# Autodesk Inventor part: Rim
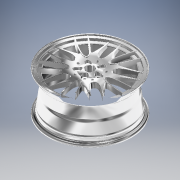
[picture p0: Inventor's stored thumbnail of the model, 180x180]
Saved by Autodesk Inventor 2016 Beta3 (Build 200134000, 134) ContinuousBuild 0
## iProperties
Shininess: 64.0
Length Units: 11269
Angle Units: 11279
Time Units: 11290
Mass Units: 11283
Length Display Precision: 3
Angle Display Precision: 2
Compacted: True
Part Number: Rim
Document SubType Name: Modeling
Created: 2003-06
Manufacturer: Standard
Standards Organization: Custom
Density: 2.71 g/cm^3
Material: Aluminum-6061
Mass: 9948.11 g
Surface Area: 8992.46 cm^2
Volume: 3670.89 cm^3
Appearance: Chrome - Polished
Density: 0.0
Volumn: 0.0
Area: 0.0
PropertySet Name: Model Information
Control State: 0
Master: False
Checked Out: False
Author: Autodesk, Inc.
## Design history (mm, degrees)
workplane "Work Plane4"
workplane "Work Plane1"
sketch "Spoke Side"
  geometry: L1 (0, -11162.344)-(0, 13420.953) reference; L2 (-1298.767, 0)-(7792.602, 0) reference; L3 (0, 55)-(10.286, 55); L4 (205.698, 37.987)-(254.302, 42.013); L5 (37.4, 37.385)-(62.6, 42.615); L6 (0, 0)-(60, 0); L7 (60, 0)-(60, 5); L8 (60, 5)-(65.959, 10); L9 (62.17, 6.821)-(69.748, 13.179); L10 (222.425, 21.138)-(237.575, 18.862); L11 (230, 40)-(230, 20); L12 (0, 55)-(0, 0); A1 r 209.241 centre (212.724, 248.526) between (210.568, 39.297) and (249.283, 42.504); A2 r 109.305 centre (27.793, 147.025) between (39.866, 38.389) and (59.938, 42.554); A3 r 90.833 centre (0, -35.833) between (50, 40) and (0, 55); A4 r 10000 centre (6493.835, -7650.444) between (68.99, 12.543) and (68.985, 12.55); A5 r 10000 centre (1715.468, 9909.054) between (223.941, 20.912) and (236.06, 19.092); 2 further points
  constraints: 20 end point, 8 midpoint, 6 point on circle, 5 centre point, 2 collinear, 2 parallel, 2 point on line, 1 perpendicular, 1 tangent, 14 other
  dimensions: "d1" = 55 distance between parallel lines of L2 L3; "d3" = 460 diameter of L11.start L1; "d4" = 40 distance from line of L2 L11.start; "d5" = 100 diameter of A3.start L1; "d6" = 50 distance from line of L2 point (110.655, 50); "d7" = 40 distance from line of L2 A3.start; "d8" = 60 distance of L6.start L6.end; "d9" = 0 distance between parallel lines of L2 L6; "d10" = 5 distance of L6.end L7.end; "d11" = 460 diameter of L11.end L1 (= d3); "d12" = 130 deg angle of L7 L8; "d13" = 5 vertical distance of L7.end L8.end; "d14" = 20 distance of L11.start L11.end
revolve "Revolution1" stored, may be unused: angle "d15" = 90 deg
sketch "Spoke Top"
  geometry: L1 (0, 35.567)-(0, -35.567) reference; L2 (-329.417, 0)-(-41.965, 0) reference; A1 r 22.668 centre (-265.684, 0) between (-282.023, 15.713) and (-282.023, -15.713); 5 further points
  constraints: 3 symmetric about line, 2 point on circle, 1 centre point, 1 point on line, 7 other
  dimensions: "d137" = 85 distance from line of L1 point (-85, 0); "d138" = 30 distance of point (-95.703, -15) point (-95.703, 15); "d139" = 40 distance of point (-231.71, -20) point (-231.71, 20)
extrude "Extrusion9" cut sketch "Spoke Top" stored distance "d141" = 10; taper "d142" = -5 deg
pattern_circular "Circular Pattern6" dims angle "d145" = 360 deg
sketch "Sketch19"
  geometry: L1 (-50, 0)-(-86.059, 0) reference; L2 (-437.715, 0)-(341.286, 0) reference; L3 (0, 398.906)-(0, -364.894) reference; L4 (0, 0)-(-268.128, 194.806) reference; L5 (-101.443, 282.759)-(-96.692, 201.808); L6 (-221.81, 29.598)-(-300.268, 9.1); A1 r 230 centre (0, 0) between (196.304, -119.853) and (196.304, 119.853) reference; A2 r 230 centre (0, 0) between (174.648, 149.66) and (-53.325, 223.733) reference; A3 r 230 centre (0, 0) between (-88.366, 212.348) and (-229.261, 18.422) reference; A4 r 230 centre (0, 0) between (-229.261, -18.422) and (-88.366, -212.348) reference; A5 r 230 centre (0, 0) between (-53.325, -223.733) and (174.648, -149.66) reference; A6 r 130.796 centre (31.504, 249.946) between (-95.482, 281.288) and (-90.944, 203.966); A7 r 130.796 centre (-227.977, -107.2) between (-222.087, 23.464) and (-297.026, 3.886); A8 r 157.848 centre (-117.742, 85.544) between (-99.068, 242.284) and (-261.039, 19.349); 10 further points
  constraints: 6 end point, 4 midpoint, 4 point on circle, 3 centre point, 3 symmetric about line, 1 horizontal alignment, 1 point on line, 13 other
  dimensions: "d147" = 100 distance of A1.centre point (-80.902, 58.779); "d148" = 10 dimension on L6.start L6.end (= d149); "d149" = 10 dimension on L5.start L5.end
extrude "Extrusion10" cut sketch "Sketch19" stored distance "d150" = 10; taper "d151" = -5 deg
pattern_circular "Circular Pattern7" dims angle "d154" = 360 deg
sketch "Sketch20"
  geometry: L1 (-300.487, 0)-(50.081, 0) reference; L2 (0, 230.697)-(0, -38.449) reference; L3 (0, 0)-(-250.021, 181.651) reference; L4 (-230.266, 187.463)-(-204.629, 181.002); L5 (-235.377, 138.681)-(-249.444, 161.066); A1 r 50.044 centre (-229.678, 135.707) between (-205.46, 179.5) and (-230.246, 185.747); A2 r 50.044 centre (-200.039, 176.501) between (-247.806, 161.578) and (-234.205, 139.935); A3 r 27.755 centre (-215.47, 156.548) between (-217.447, 184.233) and (-242.411, 149.874); 5 further points
  constraints: 6 end point, 4 midpoint, 4 point on circle, 3 centre point, 3 point on line, 3 symmetric about line, 13 other
  dimensions: "d157" = 80 distance of L3.start point (-64.721, 47.023); "d158" = 285 distance of L3.start A3.start; "d159" = 5 dimension on L4.start L4.end; "d160" = 5 dimension on L5.start L5.end (= d159); "d161" = 22 distance of point (-76.988, 42.339) point (-64.057, 60.137)
extrude "Extrusion12" join sketch "Sketch20" distance "d164" = 40; taper "d165" = 5 deg
sketch "Sketch21" dims "d166" = 5
  geometry: L1 (0, 0)-(-271.586, 197.319); A1 r 27.755 centre (-215.47, 156.548) between (-217.447, 184.233) and (-242.411, 149.874) reference; 3 further points
  constraints: 2 end point, 2 point on line, 7 other
extrude "Extrusion13" cut sketch "Sketch21" stored distance "d167" = 20; taper "d168" = -1 deg
pattern_circular "Circular Pattern8" dims angle "d171" = 360 deg
sketch "Sketch22"
  geometry: L1 (60, 0)-(60, 5) reference; L2 (60, 5)-(65.959, 10) reference; L3 (60, 0)-(60, -25.42); L4 (60, -25.42)-(230, -25.42); L5 (230, -25.42)-(230, 20); L6 (0, 55)-(0, 0) reference
  constraints: 6 end point, 1 collinear, 1 parallel, 1 perpendicular
revolve "Revolution3" sketch "Sketch22" stored, may be unused: angle "d172" = 90 deg
sketch "Sketch23"
  geometry: C1 r 225 at (0, 0); C2 r 325 at (0, 0); 1 further point
  constraints: 2 centre point, 2 coincident
  dimensions: "d173" = 450 diameter of C1; "d174" = 650 diameter of C2
extrude "Extrusion14" cut sketch "Sketch23" stored distance "d175" = 20; taper "d176" = 0 deg
workplane "Work Plane5"
sketch "Sketch24"
  geometry: L1 (0, 202.622)-(0, -33.77) reference; L2 (-278.885, 0)-(46.481, 0) reference; L3 (0, 0)-(-232.404, 168.851) reference; C1 r 12.5 at (-36.406, 26.45); 4 further points
  constraints: 5 point on line, 2 end point, 1 centre point, 1 symmetric about line, 5 other
  dimensions: "d179" = 25 diameter of C1; "d180" = 45 distance of L3.start C1.centre; "d181" = 28 distance of L3.start point (-22.652, 16.458); "d182" = 70 distance of L3.start point (-56.631, 41.145); "d183" = 32 distance of point (-47.788, 14.943) point (-28.979, 40.832)
extrude "Extrusion15" cut sketch "Sketch24" distance "d184" = 40; taper "d185" = -3 deg
sketch "Sketch25"
  geometry: L1 (0, 318.17)-(0, -318.17) reference; L2 (-321.394, 0)-(321.205, 0) reference; L3 (0, 0)-(-199.929, 145.257); 2 further points
  constraints: 2 end point, 2 point on line, 1 midpoint
  dimensions: "d186" = 36 deg angle of L2 L3; "d187" = 45 distance of L3.start point (-36.406, 26.45)
hole "Hole2" sketch "Sketch25" at (-36.406, 26.45) diameter "d188" = 12; stored, may be unused: countersink angle "d192" = 82 deg, drill point angle "d194" = 118 deg; dims "d189" = 6, "d190" = 4, "d191" = 2, "d193" = 8
sketch "Sketch26"
  geometry: L1 (0, 10.5)-(0, -10.5) reference; L2 (-87, 0)-(14.5, 0) reference; C1 r 7.5 at (-65, 0); 1 further point
  constraints: 1 centre point, 1 point on line
  dimensions: "d195" = 65 distance from line of L1 C1.centre; "d196" = 15 diameter of C1
extrude "Extrusion16" cut sketch "Sketch26" distance "d197" = 40; taper "d198" = -3 deg
pattern_circular "Circular Pattern9" dims "d201" = 360 deg
sketch "Sketch27"
  geometry: C1 r 25 at (0, 0); 1 further point
  constraints: 1 centre point, 1 coincident
  dimensions: "d202" = 50 diameter of C1
extrude "Extrusion17" cut sketch "Sketch27" stored distance "d203" = 30; taper "d204" = -5 deg
chamfer "Chamfer3" distance "d205" = 2; stored, may be unused: second distance "d206" = 2, angle "d245" = 45 deg
fillet "Fillet9" dims "d210" = 5
fillet "Fillet10" dims "d211" = 2
fillet "Fillet11" dims "d212" = 1
fillet "Fillet12" dims "d244" = 5
sketch "Rim"
  geometry: L1 (0, -207.58)-(0, 101.58) reference; L2 (205.287, 15.102)-(198.66, 13.583); L3 (191.484, -47.284)-(187.573, 24.419); L4 (194.009, 7.408)-(197.061, -48.544); L5 (210.521, -135.213)-(211.543, -143.716); L6 (207.002, -147.832)-(197.328, -67.37); L7 (211.5, 28.893)-(211.5, 22.9); L8 (212.232, 37.523)-(211.523, 29.416); L9 (221, 43)-(218.209, 43); L10 (223, 52)-(223, 55); L11 (230, 55)-(230, 52); L12 (225, 57)-(228, 57); L13 (198.023, -53.072)-(200.538, -59.666); L14 (195.866, -61.447)-(192.767, -53.321); L15 (202.292, -66.774)-(208.594, -119.191); L16 (217.5, -149)-(221, -149); L17 (221, -156)-(215, -156); L18 (224, -161)-(224, -159); L19 (230, -158)-(230, -161); L20 (228, -163)-(226, -163); L21 (221, 50)-(209, 50); L22 (197, 37)-(192, 37); L23 (-722.944, 0)-(390.999, 0) reference; L24 (197, 37)-(205, 37); L25 (207, 39)-(207, 48); A1 r 752.499 centre (-563.809, -16.57) between (187.573, 24.419) and (187.133, 31.809); A2 r 8 centre (203.5, 22.9) between (205.287, 15.102) and (211.5, 22.9); A3 r 6 centre (200, 7.734) between (198.66, 13.583) and (194.009, 7.408); A4 r 6 centre (217.5, -143) between (211.543, -143.716) and (217.5, -149); A5 r 13.486 centre (223.91, -133.603) between (210.863, -130.19) and (210.521, -135.213); A6 r 9.5 centre (201.672, -127.786) between (210.863, -130.19) and (210.019, -123.25); A7 r 13.492 centre (221.874, -116.809) between (208.594, -119.191) and (210.019, -123.25); A8 r 6 centre (217.5, 28.893) between (211.523, 29.416) and (211.5, 28.893); A9 r 6 centre (218.209, 37) between (218.209, 43) and (212.232, 37.523); A10 r 2 centre (221, 52) between (221, 50) and (223, 52); A11 r 9 centre (221, 52) between (221, 43) and (230, 52); A12 r 2 centre (225, 55) between (225, 57) and (223, 55); A13 r 2 centre (228, 55) between (230, 55) and (228, 57); A14 r 15 centre (212.039, -47.727) between (197.061, -48.544) and (198.023, -53.072); A15 r 20 centre (211.455, -46.195) between (191.484, -47.284) and (192.767, -53.321); A16 r 30 centre (172.507, -70.355) between (202.292, -66.774) and (200.538, -59.666); A17 r 25 centre (172.507, -70.355) between (197.328, -67.37) and (195.866, -61.447); A18 r 8 centre (215, -148) between (207.002, -147.832) and (215, -156); A19 r 9 centre (221, -158) between (230, -158) and (221, -149); A20 r 3 centre (221, -159) between (224, -159) and (221, -156); A21 r 2 centre (226, -161) between (224, -161) and (226, -163); A22 r 2 centre (228, -161) between (228, -163) and (230, -161); A23 r 2 centre (209, 48) between (209, 50) and (207, 48); A24 r 4.877 centre (192, 32.123) between (192, 37) and (187.133, 31.809); A25 r 2 centre (205, 39) between (205, 37) and (207, 39); 4 further points
  constraints: 50 point on circle, 46 end point, 45 tangent, 25 centre point, 3 parallel, 1 perpendicular
  dimensions: "d266" = 2 radius of A23; "d267" = 220 distance between parallel lines of L20 L12; "d268" = 7 distance between parallel lines of L17 L16; "d269" = 5 distance between parallel lines of L6 L5; "d270" = 5 distance between parallel lines of L6 L15; "d271" = 5 distance between parallel lines of L14 L13; "d272" = 5.5 distance between parallel lines of L3 L4; "d273" = 50 distance between parallel lines of L23 L21; "d274" = 7 distance between parallel lines of L9 L21; "d276" = 8 radius of A2; "d277" = 9 radius of A11; "d278" = 2 radius of A13; "d279" = 2 radius of A12; "d280" = 2 radius of A10; "d282" = 6 radius of A3; "d283" = 15 radius of A14; "d284" = 20 radius of A15; "d285" = 30 radius of A16; "d286" = 25 radius of A17; "d287" = 9.5 radius of A6; "d288" = 6 radius of A4; "d289" = 9 radius of A19; "d290" = 2 radius of A22; "d291" = 2 radius of A21; "d292" = 3 radius of A20; "d293" = 8 radius of A18; "d294" = 57 distance between parallel lines of L23 L12; "d295" = 7 distance between parallel lines of L20 L17; "d296" = 460 diameter of L11 L1; "d298" = 460 diameter of L19 L1; "d299" = 18.5 distance between parallel lines of L7 L11; "d300" = 9 distance from line of A11.centre L11 (derived); "d301" = 21 distance from line of L11 A23.centre; "d304" = 38 distance from line of L11 A24.centre; "d305" = 30 distance from line of L11 A3.centre; "d306" = 7 distance between parallel lines of L11 L10; "d307" = 6 distance between parallel lines of L18 L19; "d308" = 9 distance from line of A19.centre L19 (derived); "d309" = 12.5 distance from line of A4.centre L19; "d310" = 15 distance from line of A18.centre L19; "d311" = 46.19501 distance from line of L23 A15.centre; "d312" = 47.72741 distance from line of L23 A14.centre; "d313" = 70.3547 distance from line of L23 A17.centre; "d314" = 77.49796 distance from line of L23 point (212.258, -77.498); "d332" = 20 distance between parallel lines of L12 L22; "d333" = 2 radius of A25
revolve "Revolution4" stored, may be unused: angle "d214" = 90 deg
sketch "Sketch33"
  geometry: L1 (208, 21)-(211, 21) reference; L2 (199, 8.5)-(199, 12) reference; L3 (185.213, 1.521)-(193.716, 2.543) reference; L4 (116.774, -6.708)-(169.191, -0.406) reference; L5 (103.072, -10.977)-(109.666, -8.462) reference; L6 (42.592, -14.991)-(98.544, -11.939) reference; L7 (34.898, -3.713)-(36.417, -10.34) reference; L8 (21.107, 2.5)-(27.1, 2.5) reference; L9 (12.477, 3.232)-(20.584, 2.523) reference; L10 (7, 12)-(7, 9.209) reference; L11 (-5, 21)-(-2, 21) reference; L12 (258.433, -209)-(-59.6, -209) reference; A1 r 9 centre (208, 12) between (208, 21) and (199, 12) reference; A2 r 6 centre (193, 8.5) between (193.716, 2.543) and (199, 8.5) reference; A3 r 13.486 centre (183.603, 14.91) between (180.19, 1.863) and (185.213, 1.521) reference; A4 r 9.5 centre (177.786, -7.328) between (180.19, 1.863) and (173.25, 1.019) reference; A5 r 13.492 centre (166.809, 12.874) between (169.191, -0.406) and (173.25, 1.019) reference; A6 r 30 centre (120.355, -36.493) between (116.774, -6.708) and (109.666, -8.462) reference; A7 r 15 centre (97.727, 3.039) between (98.544, -11.939) and (103.072, -10.977) reference; A8 r 6 centre (42.266, -9) between (36.417, -10.34) and (42.592, -14.991) reference; A9 r 8 centre (27.1, -5.5) between (34.898, -3.713) and (27.1, 2.5) reference; A10 r 6 centre (21.107, 8.5) between (20.584, 2.523) and (21.107, 2.5) reference; A11 r 6 centre (13, 9.209) between (7, 9.209) and (12.477, 3.232) reference; A12 r 9 centre (-2, 12) between (7, 12) and (-2, 21) reference
feature "RevolutionSrf1" sketch "Sketch33" dims angle "d315" = 90 deg
split "Split1"
pattern_circular "Circular Pattern11" dims angle "d317" = 360 deg
sketch "Sketch34"
  geometry: L1 (0, -399.846)-(0, 399.138) reference; L2 (-404.857, 0)-(355.966, 0) reference; L3 (0, 0)-(28.191, 10.261); L4 (0, 0)-(28.191, -10.261); L5 (28.191, 10.261)-(49.334, 17.956); L6 (28.191, -10.261)-(49.334, -17.956); C1 r 60 at (0, 0) reference; A1 r 52.5 centre (0, 0) between (49.334, 17.956) and (49.334, -17.956); A2 r 30 centre (0, 0) between (28.191, -10.261) and (28.191, 10.261); A3 r 52.5 centre (0, 0) between (52.5, 0) and (49.334, 17.956); A4 r 52.5 centre (0, 0) between (49.334, -17.956) and (52.5, 0); A5 r 30 centre (0, 0) between (0, -30) and (28.191, -10.261); A6 r 30 centre (0, 0) between (28.191, 10.261) and (0, -30)
  constraints: 12 point on circle, 8 end point, 6 centre point, 3 coincident, 3 point on line
  dimensions: "d319" = 40 deg angle of L4 L3; "d320" = 20 deg angle of L2 L3 (derived); "d321" = 105 diameter of A1; "d322" = 60 diameter of A2
extrude "Extrusion19" cut sketch "Sketch34" distance "d323" = 15; taper "d324" = -3 deg
fillet "Fillet18" dims "d325" = 2
chamfer "Chamfer5" distance "d326" = 2; stored, may be unused: second distance "d327" = 2, angle "d328" = 45 deg
pattern_circular "Circular Pattern12" dims "d330" = 360 deg
fillet "Fillet19" dims "d334" = 2
body "Solid1"
node "Projected Loop2"
body "Srf1"
other parameters: "d155" = 52
